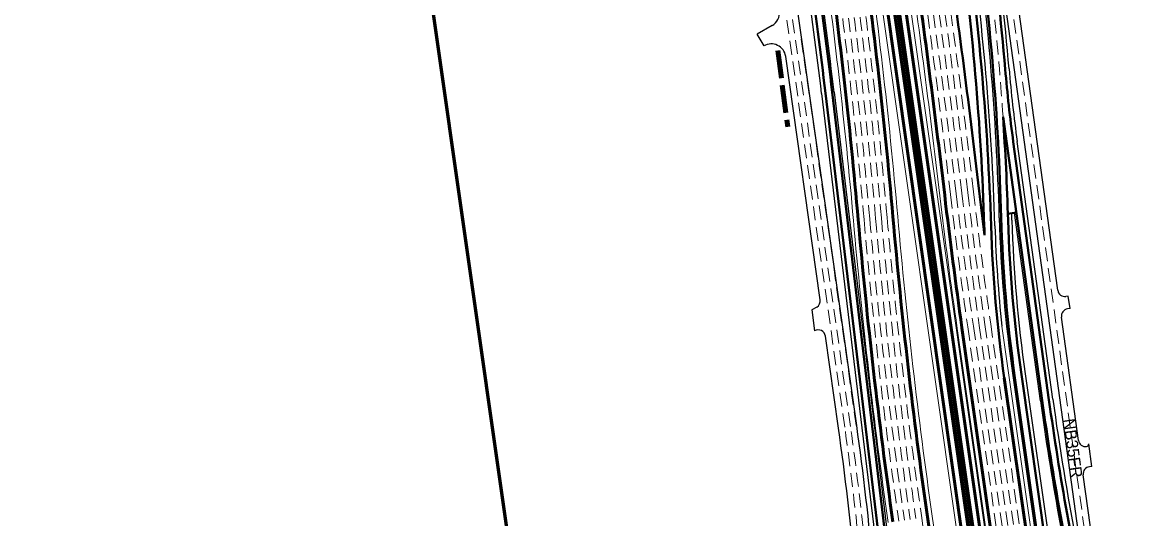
# Model space of a CAD drawing. Extents: x 2329387 to 2347382, y 6951580 to 6987999.
# Drawn here: x 2329937 to 2332250, y 6965820 to 6966846 of the extents above; entities that cross this region are included whole.
import ezdxf

# ---------------------------------------------------------------- set-up
doc = ezdxf.new("R2010")
doc.units = 0
doc.header["$LTSCALE"] = 9.6
doc.linetypes.add('LONG_DASHED', pattern=[7.5, 6, -1.5])
doc.linetypes.add('MEDIUM_DASHED', pattern=[4.5, 3, -1.5])
for name, color, linetype, lineweight in [('26', 7, 'Continuous', 53), ('27', 7, 'Continuous', 40), ('28', 7, 'Continuous', 25), ('31', 7, 'Continuous', 53), ('50', 7, 'MEDIUM_DASHED', 13), ('59', 7, 'LONG_DASHED', 90), ('62', 7, 'Continuous', 60)]:
    doc.layers.add(name, color=color, linetype=linetype, lineweight=lineweight)
doc.layers.add('40', color=7, linetype='Continuous')

msp = doc.modelspace()

# ---------------------------------------------------------------- linework, layer by layer
at = {"layer": '26', "lineweight": 13}
for p, q in [((2331870.105, 6966212.955), (2332003.684, 6965277.65)), ((2331962.309, 6966218.061), (2332094.76, 6965290.657)), ((2331818.462, 6965824.822), (2331918.246, 6965126.152))]:
    msp.add_line(p, q, dxfattribs=at)
at = {"layer": '26'}
for p, q in [((2331880.005, 6966214.369), (2332013.584, 6965279.064)), ((2331967.521, 6966110.841), (2332084.861, 6965289.244)), ((2331808.563, 6965823.408), (2331908.346, 6965124.738))]:
    msp.add_line(p, q, dxfattribs=at)
for centre, radius, start, end in [((2320321.739, 6965443.45), 11459.156, 5.00662, 8.12777), ((2309084.586, 6963796.291), 22918.312, 6.74594, 8.12795), ((2320321.739, 6965443.45), 11387.156, 5.00662, 7.99663), ((2343224.051, 6967834.513), 11459.156, 186.74594, 188.12795), ((2343152.609, 6967443.552), 11531.156, 185.00662, 188.12795), ((2343152.609, 6967443.552), 11459.156, 185.00662, 188.12795)]:
    msp.add_arc(centre, radius, start, end, dxfattribs=at)
at = {"layer": '26', "lineweight": 13}
for centre, radius, start, end in [((2320321.739, 6965443.45), 11469.156, 5.00662, 8.12814), ((2309084.586, 6963796.291), 22908.312, 6.74594, 8.12795), ((2320321.739, 6965443.45), 11377.156, 5.00662, 7.99651), ((2343224.051, 6967834.513), 11469.156, 186.74594, 188.12795), ((2343152.609, 6967443.552), 11541.156, 185.00662, 188.12795), ((2343152.609, 6967443.552), 11449.156, 185.00662, 188.12795)]:
    msp.add_arc(centre, radius, start, end, dxfattribs=at)
at = {"layer": '27', "lineweight": 25}
for p, q in [((2331589.775, 6966698.599), (2331783.084, 6965089.223)), ((2331615.589, 6966701.7), (2331808.898, 6965092.328)), ((2332067.846, 6966066.898), (2331994.166, 6966599.587)), ((2332042.091, 6966063.336), (2331988.324, 6966452.055)), ((2331985.027, 6966115.578), (2332072.021, 6965506.454)), ((2332010.766, 6966119.254), (2332097.771, 6965510.058))]:
    msp.add_line(p, q, dxfattribs=at)
at = {"layer": '27'}
for p, q in [((2331597.718, 6966699.553), (2331791.027, 6965090.177)), ((2331611.618, 6966701.223), (2331804.926, 6965091.851)), ((2332046.053, 6966063.884), (2331964.956, 6966650.197)), ((2332059.921, 6966065.802), (2331986.241, 6966598.491)), ((2331974.952, 6966450.206), (2331992.287, 6966452.603)), ((2331988.987, 6966116.144), (2332075.967, 6965507.123)), ((2332002.846, 6966118.123), (2332089.804, 6965509.258))]:
    msp.add_line(p, q, dxfattribs=at)
for centre, radius, start, end in [((2339406.145, 6959556.474), 7976, 170.51466, 170.51466), ((2326225.909, 6966280.498), 5737.578, 1.61382, 7.87499), ((2309084.586, 6963796.291), 22990.312, 6.74594, 8.12795), ((2326213.511, 6966242.625), 5715.578, 1.82199, 8.12795), ((2326213.511, 6966242.625), 5729.578, 1.82199, 8.12795), ((2326260.379, 6966264.837), 5729.578, 4.84688, 7.87499), ((2320220.341, 6965332.97), 11459.156, 6.84922, 8.12795), ((2320220.341, 6965332.97), 11473.156, 6.84922, 8.12795), ((2334824.013, 6966991.002), 2864.789, 184.84688, 187.87499), ((2326260.379, 6966264.837), 5717.578, 1.72481, 3.86462), ((2343224.051, 6967834.513), 11387.156, 186.74594, 187.206), ((2334838.858, 6966523.159), 2878.789, 181.61382, 188.12794), ((2334838.858, 6966523.159), 2864.789, 181.72481, 188.12794), ((2334803.532, 6966515.877), 2878.789, 181.82199, 182.18461), ((2334803.532, 6966515.877), 2864.789, 181.82199, 188.12795), ((2337735.465, 6966850.824), 5743.578, 187.87499, 192.65581), ((2337735.465, 6966850.824), 5729.578, 187.87499, 192.65581)]:
    msp.add_arc(centre, radius, start, end, dxfattribs=at)
at = {"layer": '27', "lineweight": 25}
for centre, radius, start, end in [((2326225.909, 6966280.498), 5733.578, 1.61382, 7.87499), ((2326213.511, 6966242.625), 5737.578, 1.82199, 8.12795), ((2326260.379, 6966264.837), 5737.578, 4.84688, 7.87499), ((2320220.341, 6965332.97), 11451.156, 6.84922, 8.12795), ((2320220.341, 6965332.97), 11477.156, 6.84922, 8.12795), ((2334824.013, 6966991.002), 2856.789, 184.8436, 187.87499), ((2334838.858, 6966523.159), 2882.789, 181.61382, 188.12794), ((2326260.379, 6966264.837), 5725.578, 1.72481, 1.86634), ((2334838.858, 6966523.159), 2856.789, 181.72481, 188.12794), ((2334803.532, 6966515.877), 2856.789, 181.82199, 185.98388), ((2337735.465, 6966850.824), 5747.578, 187.87499, 192.65581), ((2337735.465, 6966850.824), 5721.578, 187.87499, 190.89172)]:
    msp.add_arc(centre, radius, start, end, dxfattribs=at)
at = {"layer": '28'}
for p, q in [((2332078.029, 6966291.919), (2331740.454, 6968732.516)), ((2332123.879, 6965770.67), (2331828.88, 6967903.45)), ((2331662.241, 6966012.534), (2331472.552, 6967346.767)), ((2331487.489, 6966838.89), (2331456.702, 6966820.956)), ((2331470.6, 6966797.097), (2331456.702, 6966820.956)), ((2331586.918, 6966272.364), (2331515.402, 6966775.397)), ((2332099.895, 6966279.801), (2332094.942, 6966279.116)), ((2332103.458, 6966254.046), (2332099.895, 6966279.801)), ((2331579.622, 6966257.294), (2331569.595, 6966251.449)), ((2331569.595, 6966251.449), (2331575.163, 6966207.987)), ((2332103.458, 6966254.046), (2332098.505, 6966253.361)), ((2332120.926, 6965981.782), (2332085.701, 6966236.447)), ((2331624.619, 6966007.185), (2331597.61, 6966197.164)), ((2332148.547, 6965928.06), (2332142.107, 6965974.617)), ((2332148.547, 6965928.06), (2332143.594, 6965927.375)), ((2332209.846, 6965338.909), (2332130.791, 6965910.461))]:
    msp.add_line(p, q, dxfattribs=at)
for centre, radius, start, end in [((2331472.388, 6966864.812), 30, 300.22184, 8.09153), ((2331485.701, 6966771.174), 30, 8.09153, 120.22184), ((2332092.887, 6966293.974), 15, 187.87499, 277.87499), ((2331572.068, 6966270.253), 15, 300.23814, 8.09153), ((2332100.56, 6966238.502), 15, 97.87499, 187.87499), ((2331582.759, 6966195.053), 15, 8.09153, 120.42586), ((2325953.072, 6965200.86), 5728.578, 2.10758, 8.09153), ((2325953.072, 6965200.86), 5766.578, 2.10758, 8.09153), ((2332135.784, 6965983.837), 15, 187.87499, 277.87499), ((2332137.155, 6965973.932), 5, 277.87499, 7.87499), ((2332145.649, 6965912.516), 15, 97.87499, 187.87499)]:
    msp.add_arc(centre, radius, start, end, dxfattribs=at)
at = {"layer": '31'}
for p, q in [((2331690.26, 6967217.584), (2331941.267, 6965460.063)), ((2331700.159, 6967218.998), (2331951.166, 6965461.481)), ((2331714.019, 6967220.977), (2331965.025, 6965463.46)), ((2331676.4, 6967215.605), (2331927.407, 6965458.088))]:
    msp.add_line(p, q, dxfattribs=at)
at = {"layer": '31', "lineweight": 13}
for p, q in [((2331694.22, 6967218.149), (2331945.226, 6965460.633)), ((2331696.2, 6967218.432), (2331947.206, 6965460.916)), ((2331723.658, 6967224.211), (2331974.925, 6965464.874)), ((2331666.501, 6967214.191), (2331917.507, 6965456.674))]:
    msp.add_line(p, q, dxfattribs=at)
at = {"layer": '50'}
for p, q in [((2331637.49, 6966009.015), (2330956.52, 6970798.829)), ((2332198.633, 6965325.094), (2331727.576, 6968730.735)), ((2331649.37, 6966010.704), (2331444.619, 6967450.882)), ((2331661.251, 6966012.393), (2331471.562, 6967346.626)), ((2331939.402, 6966222.852), (2332072.981, 6965287.547)), ((2331891.884, 6966216.065), (2332025.463, 6965280.76)), ((2331903.764, 6966217.762), (2332037.343, 6965282.457)), ((2331915.643, 6966219.458), (2332049.222, 6965284.154)), ((2331927.523, 6966221.155), (2332061.102, 6965285.85)), ((2331796.683, 6965821.712), (2331896.467, 6965123.041))]:
    msp.add_line(p, q, dxfattribs=at)
for centre, radius, start, end in [((2320321.739, 6965443.45), 11399.156, 5.00662, 8.12804), ((2320321.739, 6965443.45), 11411.156, 5.00662, 8.12782), ((2320321.739, 6965443.45), 11423.156, 5.00662, 8.12795), ((2320321.739, 6965443.45), 11435.156, 5.00662, 8.12779), ((2320321.739, 6965443.45), 11447.156, 5.00662, 8.1281), ((2309084.586, 6963796.291), 22930.312, 6.74594, 8.12795), ((2309084.586, 6963796.291), 22942.312, 6.74594, 8.12795), ((2309084.586, 6963796.291), 22954.312, 6.74594, 8.12795), ((2309084.586, 6963796.291), 22966.312, 6.74594, 8.12795), ((2309084.586, 6963796.291), 22978.312, 6.74594, 8.12795), ((2326260.379, 6966264.837), 5717.578, 3.86462, 7.87499), ((2343224.051, 6967834.513), 11447.156, 186.74594, 188.12795), ((2343224.051, 6967834.513), 11435.156, 186.74594, 188.12795), ((2343224.051, 6967834.513), 11423.156, 186.74594, 188.12795), ((2343224.051, 6967834.513), 11411.156, 186.74594, 188.12795), ((2343224.051, 6967834.513), 11399.156, 186.74594, 188.12795), ((2343152.609, 6967443.552), 11519.156, 185.00662, 188.12795), ((2343152.609, 6967443.552), 11507.156, 185.00662, 188.12795), ((2343152.609, 6967443.552), 11495.156, 185.00662, 188.12795), ((2343152.609, 6967443.552), 11483.156, 185.00662, 188.12795), ((2343152.609, 6967443.552), 11471.156, 185.00662, 188.12795), ((2325953.072, 6965200.86), 5741.578, 2.10758, 8.09153), ((2325953.072, 6965200.86), 5753.578, 2.10758, 8.09153)]:
    msp.add_arc(centre, radius, start, end, dxfattribs=at)
at = {"layer": '59'}
msp.add_line((2331498.867, 6966787.22), (2331519.712, 6966630.08), dxfattribs=at)
at = {"layer": '62'}
msp.add_lwpolyline([(2329936.564, 6972812.843), (2331011.084, 6965289.186), (2332891.999, 6965557.816), (2331817.479, 6973081.473)], close=True, dxfattribs=at)

# ---------------------------------------------------------------- texts
at = {"layer": '40'}
msp.add_text('NB35FR', height=24, rotation=277.862, dxfattribs=at).set_placement((2332089.051, 6966024.93))

doc.saveas('drawing.dxf')
